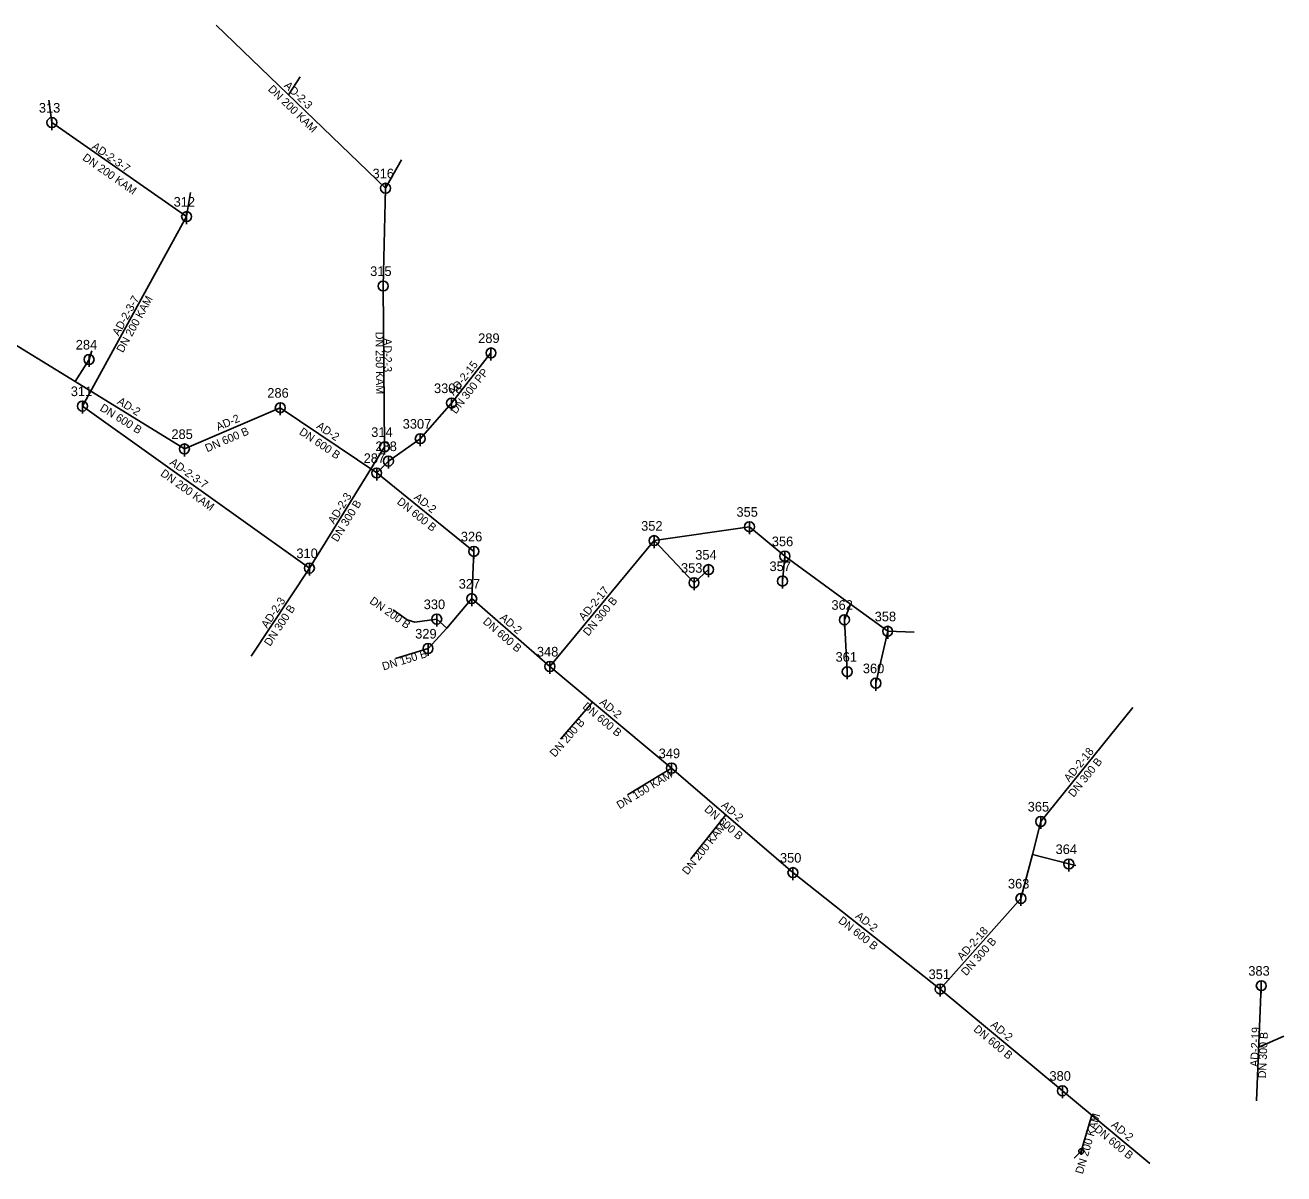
# Model space of a CAD drawing. Extents: x -443519 to -443022, y -1121479 to -1120928.
# Drawn here: x -443274.4 to -443022.1, y -1121478.8 to -1121248.5 of the extents above; entities that cross this region are included whole.
import ezdxf

# ---------------------------------------------------------------- set-up
doc = ezdxf.new("R2010")
doc.units = 0
for name, color, linetype in [('_pripojka_kanal_jednotna_priblizne_', 7, 'Continuous'), ('_stoka_jednotna_smvak_prevzato_z_dokumentace_', 7, 'Continuous'), ('Default', 7, 'Continuous'), ('MoLevel 119', 7, 'Continuous'), ('MoLevel 120', 7, 'Continuous'), ('MoLevel 124', 7, 'Continuous'), ('MoLevel 57', 7, 'Continuous'), ('MoLevel 68', 7, 'Continuous'), ('MoLevel 69', 7, 'Continuous')]:
    doc.layers.add(name, color=color, linetype=linetype)

# ---------------------------------------------------------------- blocks, each defined once
blk = doc.blocks.new('_sachta_kanal_prip_')
at = {"layer": 'Default'}
blk.add_line((0, 0.00005), (0, -0.000075), dxfattribs=at)
blk.add_circle((0, 0), 0.00005, dxfattribs=at)
blk = doc.blocks.new('_sachta_kanal_prevzato_z_dokumentace_')
at = {"layer": 'Default'}
blk.add_line((0, 0.00005), (0, -0.000075), dxfattribs=at)
blk.add_circle((0, 0), 0.00005, dxfattribs=at)

msp = doc.modelspace()

# ---------------------------------------------------------------- linework, layer by layer
at = {"layer": '_pripojka_kanal_jednotna_priblizne_'}
for p, q in [((-443219.3, -1121258.89), (-443221.64, -1121262.45)), ((-443269.7, -1121263.54), (-443269.06, -1121268.04)), ((-443198.99, -1121275.48), (-443202.16, -1121281.21)), ((-443241.26, -1121282.07), (-443242.04, -1121286.89)), ((-443261.02, -1121313.82), (-443261.61, -1121315.53)), ((-443200.19, -1121375.46), (-443193.65, -1121373.46)), ((-443167.1, -1121391.65), (-443160.64, -1121384.22)), ((-443153.63, -1121402.8), (-443144.83, -1121397.44)), ((-443140.98, -1121415.6), (-443133.93, -1121406.81)), ((-443063.75, -1121416.92), (-443065.17, -1121416.65)), ((-443022.07, -1121451.15), (-443027.09, -1121453.38)), ((-443062.68, -1121474.21), (-443060.56, -1121466.99)), ((-443064.09, -1121475.63), (-443062.68, -1121474.21))]:
    msp.add_line(p, q, dxfattribs=at)
msp.add_lwpolyline([(-443200.62, -1121365.73), (-443197.8, -1121367.7), (-443196.29, -1121368.19), (-443191.9, -1121367.57)], dxfattribs=at)
at = {"layer": '_stoka_jednotna_smvak_prevzato_z_dokumentace_'}
for p, q in [((-443236.1, -1121248.52), (-443202.16, -1121281.21)), ((-443269.06, -1121268.04), (-443242.04, -1121286.89)), ((-443202.16, -1121281.21), (-443202.64, -1121300.8)), ((-443242.04, -1121286.89), (-443262.93, -1121324.87)), ((-443202.64, -1121300.8), (-443202.38, -1121333.06)), ((-443264.37, -1121319.96), (-443279.68, -1121310.61)), ((-443181.02, -1121314.22), (-443188.92, -1121324.26)), ((-443261.61, -1121315.53), (-443264.37, -1121319.96)), ((-443242.49, -1121333.46), (-443264.37, -1121319.96)), ((-443188.92, -1121324.26), (-443195.2, -1121331.4)), ((-443262.93, -1121324.87), (-443217.43, -1121357.34)), ((-443223.26, -1121325.19), (-443242.49, -1121333.46)), ((-443203.94, -1121338.28), (-443223.26, -1121325.19)), ((-443195.2, -1121331.4), (-443201.58, -1121335.89)), ((-443202.38, -1121333.06), (-443217.43, -1121357.34)), ((-443201.58, -1121335.89), (-443203.94, -1121338.28)), ((-443184.46, -1121353.99), (-443203.94, -1121338.28)), ((-443129.2, -1121349.05), (-443148.32, -1121351.84)), ((-443122.11, -1121354.95), (-443129.2, -1121349.05)), ((-443148.32, -1121351.84), (-443169.21, -1121377.06)), ((-443140.32, -1121360.28), (-443148.32, -1121351.84)), ((-443184.89, -1121363.46), (-443184.46, -1121353.99)), ((-443217.43, -1121357.34), (-443229.09, -1121374.97)), ((-443122.58, -1121359.94), (-443122.11, -1121354.95)), ((-443108.92, -1121364.58), (-443122.11, -1121354.95)), ((-443137.41, -1121357.65), (-443140.32, -1121360.28)), ((-443189.87, -1121369.35), (-443184.89, -1121363.46)), ((-443169.21, -1121377.06), (-443184.89, -1121363.46)), ((-443110.16, -1121367.7), (-443108.92, -1121364.58)), ((-443101.49, -1121370.01), (-443108.92, -1121364.58)), ((-443193.65, -1121373.46), (-443189.87, -1121369.35)), ((-443191.9, -1121367.57), (-443189.87, -1121369.35)), ((-443109.6, -1121378.11), (-443110.16, -1121367.7)), ((-443103.85, -1121380.41), (-443101.49, -1121370.01)), ((-443096.17, -1121370.2), (-443101.49, -1121370.01)), ((-443144.83, -1121397.44), (-443169.21, -1121377.06)), ((-443052.32, -1121385.25), (-443070.81, -1121408.13)), ((-443120.48, -1121418.38), (-443144.83, -1121397.44)), ((-443070.81, -1121408.13), (-443072.43, -1121414.75)), ((-443072.43, -1121414.75), (-443074.77, -1121423.56)), ((-443065.17, -1121416.65), (-443072.43, -1121414.75)), ((-443090.95, -1121441.72), (-443120.48, -1121418.38)), ((-443074.77, -1121423.56), (-443090.95, -1121441.72)), ((-443066.45, -1121462.1), (-443090.95, -1121441.72)), ((-443026.58, -1121441.04), (-443027.54, -1121464.1)), ((-443048.91, -1121476.66), (-443066.45, -1121462.1))]:
    msp.add_line(p, q, dxfattribs=at)

# ---------------------------------------------------------------- block references
at = {"layer": 'MoLevel 119', "xscale": 20000, "yscale": 20000}
for p in [(-443269.06, -1121268.04), (-443202.16, -1121281.21), (-443242.04, -1121286.89), (-443202.64, -1121300.8), (-443181.02, -1121314.22), (-443261.61, -1121315.53), (-443262.93, -1121324.87), (-443223.26, -1121325.19), (-443188.92, -1121324.26), (-443202.38, -1121333.06), (-443195.2, -1121331.4), (-443242.49, -1121333.46), (-443201.58, -1121335.89), (-443203.94, -1121338.28), (-443129.2, -1121349.05), (-443148.32, -1121351.84), (-443184.46, -1121353.99), (-443122.11, -1121354.95), (-443217.43, -1121357.34), (-443137.41, -1121357.65), (-443140.32, -1121360.28), (-443122.58, -1121359.94), (-443184.89, -1121363.46), (-443191.9, -1121367.57), (-443110.16, -1121367.7), (-443101.49, -1121370.01), (-443193.65, -1121373.46), (-443169.21, -1121377.06), (-443109.6, -1121378.11), (-443103.85, -1121380.41), (-443144.83, -1121397.44), (-443070.81, -1121408.13), (-443120.48, -1121418.38), (-443065.17, -1121416.65), (-443074.77, -1121423.56), (-443026.58, -1121441.04), (-443090.95, -1121441.72), (-443066.45, -1121462.1)]:
    msp.add_blockref('_sachta_kanal_prevzato_z_dokumentace_', p, dxfattribs=at)
at = {"layer": 'MoLevel 57', "xscale": 10000, "yscale": 10000}
msp.add_blockref('_sachta_kanal_prip_', (-443062.68, -1121474.21), dxfattribs=at)

# ---------------------------------------------------------------- texts
at = {"layer": 'MoLevel 120'}
for s, p in [('313', (-443271.67, -1121266.04)), ('316', (-443204.77, -1121279.21)), ('312', (-443244.65, -1121284.89)), ('315', (-443205.25, -1121298.8)), ('284', (-443264.27, -1121313.53)), ('289', (-443183.59, -1121312.22)), ('311', (-443265.27, -1121322.87)), ('286', (-443225.87, -1121323.19)), ('3308', (-443192.45, -1121322.26)), ('285', (-443245.1, -1121331.46)), ('314', (-443205.04, -1121331.06)), ('3307', (-443198.73, -1121329.4)), ('288', (-443204.19, -1121333.89)), ('287', (-443206.55, -1121336.28)), ('355', (-443131.81, -1121347.05)), ('352', (-443150.92, -1121349.85)), ('326', (-443187.07, -1121351.99)), ('356', (-443124.72, -1121352.95)), ('310', (-443220.04, -1121355.34)), ('354', (-443140.07, -1121355.65)), ('353', (-443142.93, -1121358.28)), ('357', (-443125.19, -1121357.94)), ('327', (-443187.5, -1121361.46)), ('330', (-443194.51, -1121365.57)), ('362', (-443112.77, -1121365.7)), ('358', (-443104.1, -1121368.01)), ('329', (-443196.22, -1121371.46)), ('348', (-443171.82, -1121375.06)), ('361', (-443111.94, -1121376.11)), ('360', (-443106.47, -1121378.41)), ('349', (-443147.4, -1121395.44)), ('365', (-443073.42, -1121406.13)), ('364', (-443067.83, -1121414.65)), ('350', (-443123.09, -1121416.38)), ('363', (-443077.38, -1121421.56)), ('351', (-443093.29, -1121439.72)), ('383', (-443029.19, -1121439.04)), ('380', (-443069.06, -1121460.1))]:
    msp.add_text(s, height=1.926, dxfattribs=at).set_placement(p)
at = {"layer": 'MoLevel 124'}
for s, rotation, p in [('DN 200 B', 324.9836, (-443205.5, -1121364.27)), ('DN 150 B', 17.0267, (-443202.57, -1121377.87)), ('DN 200 B', 49.018, (-443168.2, -1121395.36)), ('DN 150 KAM', 31.3561, (-443155.23, -1121405.7)), ('DN 200 KAM', 51.2545, (-443141.62, -1121418.96)), ('DN 200 KAM', 73.6236, (-443062.39, -1121478.92))]:
    msp.add_text(s, height=1.605, rotation=rotation, dxfattribs=at).set_placement(p)
at = {"layer": 'MoLevel 68'}
for s, rotation, p in [('DN 200 KAM', 316.0737, (-443225.84, -1121261.5)), ('DN 200 KAM', 325.0983, (-443263.06, -1121275.42)), ('DN 200 KAM', 61.1845, (-443254.81, -1121314.3)), ('DN 250 KAM', 270.4639, (-443204.17, -1121309.98)), ('DN 300 PP', 51.8025, (-443188.06, -1121326.56)), ('DN 600 B', 328.3286, (-443259.57, -1121325.66)), ('DN 600 B', 23.2759, (-443237.93, -1121334.14)), ('DN 600 B', 325.8816, (-443219.62, -1121330.39)), ('DN 200 KAM', 324.4873, (-443247.43, -1121338.69)), ('DN 300 B', 58.2048, (-443211.81, -1121352.23)), ('DN 600 B', 321.1141, (-443200.01, -1121344.29)), ('DN 300 B', 56.5212, (-443225.3, -1121373.14)), ('DN 300 B', 50.3653, (-443161.5, -1121371.08)), ('DN 600 B', 319.0665, (-443182.77, -1121368.26)), ('DN 600 B', 320.1067, (-443162.79, -1121385.31)), ('DN 300 B', 51.0589, (-443064.2, -1121403.4)), ('DN 600 B', 319.3058, (-443138.39, -1121405.89)), ('DN 600 B', 321.6771, (-443111.53, -1121428.27)), ('DN 300 B', 48.3037, (-443085.74, -1121439.18)), ('DN 600 B', 320.2468, (-443084.41, -1121449.99)), ('DN 300 B', 87.6202, (-443025.65, -1121459.63)), ('DN 600 B', 320.3111, (-443060.24, -1121470.04))]:
    msp.add_text(s, height=1.605, rotation=rotation, dxfattribs=at).set_placement(p)
at = {"layer": 'MoLevel 69'}
for s, rotation, p in [('AD-2-3', 316.0737, (-443222.63, -1121260.76)), ('AD-2-3-7', 325.0983, (-443261.2, -1121273.16)), ('AD-2-3-7', 61.1845, (-443255.66, -1121310.93)), ('AD-2-3', 270.4639, (-443202.54, -1121311.27)), ('AD-2-15', 51.8025, (-443188.47, -1121322.88)), ('AD-2', 328.3286, (-443256.1, -1121324.32)), ('AD-2', 23.2759, (-443235.72, -1121329.84)), ('AD-2', 325.8816, (-443216.16, -1121329.2)), ('AD-2-3-7', 324.4873, (-443245.57, -1121336.45)), ('AD-2-3', 58.2048, (-443212.47, -1121348.65)), ('AD-2', 321.1141, (-443196.59, -1121343.39)), ('AD-2-17', 50.3653, (-443162.37, -1121368.01)), ('AD-2-3', 56.5212, (-443225.9, -1121369.53)), ('AD-2', 319.0665, (-443179.38, -1121367.48)), ('AD-2', 320.1067, (-443159.39, -1121384.47)), ('AD-2-18', 51.0589, (-443065.08, -1121400.34)), ('AD-2', 319.3058, (-443135, -1121405.09)), ('AD-2', 321.6771, (-443108.11, -1121427.33)), ('AD-2-18', 48.3037, (-443086.56, -1121436.08)), ('AD-2', 320.2468, (-443081, -1121449.13)), ('AD-2-19', 87.6202, (-443027.22, -1121457.35)), ('AD-2', 320.3111, (-443056.83, -1121469.18))]:
    msp.add_text(s, height=1.605, rotation=rotation, dxfattribs=at).set_placement(p)

doc.saveas('drawing.dxf')
